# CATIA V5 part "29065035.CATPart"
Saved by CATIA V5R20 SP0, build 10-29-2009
Part number: 29065035
Definition: NONE
Nomenclature: 29065035
Source: Unknown
Description: 29065035
Bounding box of the stored display mesh (mm): x -17.5 to 44.548, y -46.5 to 81.048, z -36.5 to 36.5
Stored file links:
  C:\Users\Utente\Desktop\IO LAVORO\3D X SITO CF\X SITO\PLASTICA\RF1\29065035.CATPart
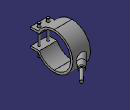
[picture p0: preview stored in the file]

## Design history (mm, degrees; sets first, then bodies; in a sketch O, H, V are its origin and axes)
Body1 "29065035" (main body)
  Solid1: solid without history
